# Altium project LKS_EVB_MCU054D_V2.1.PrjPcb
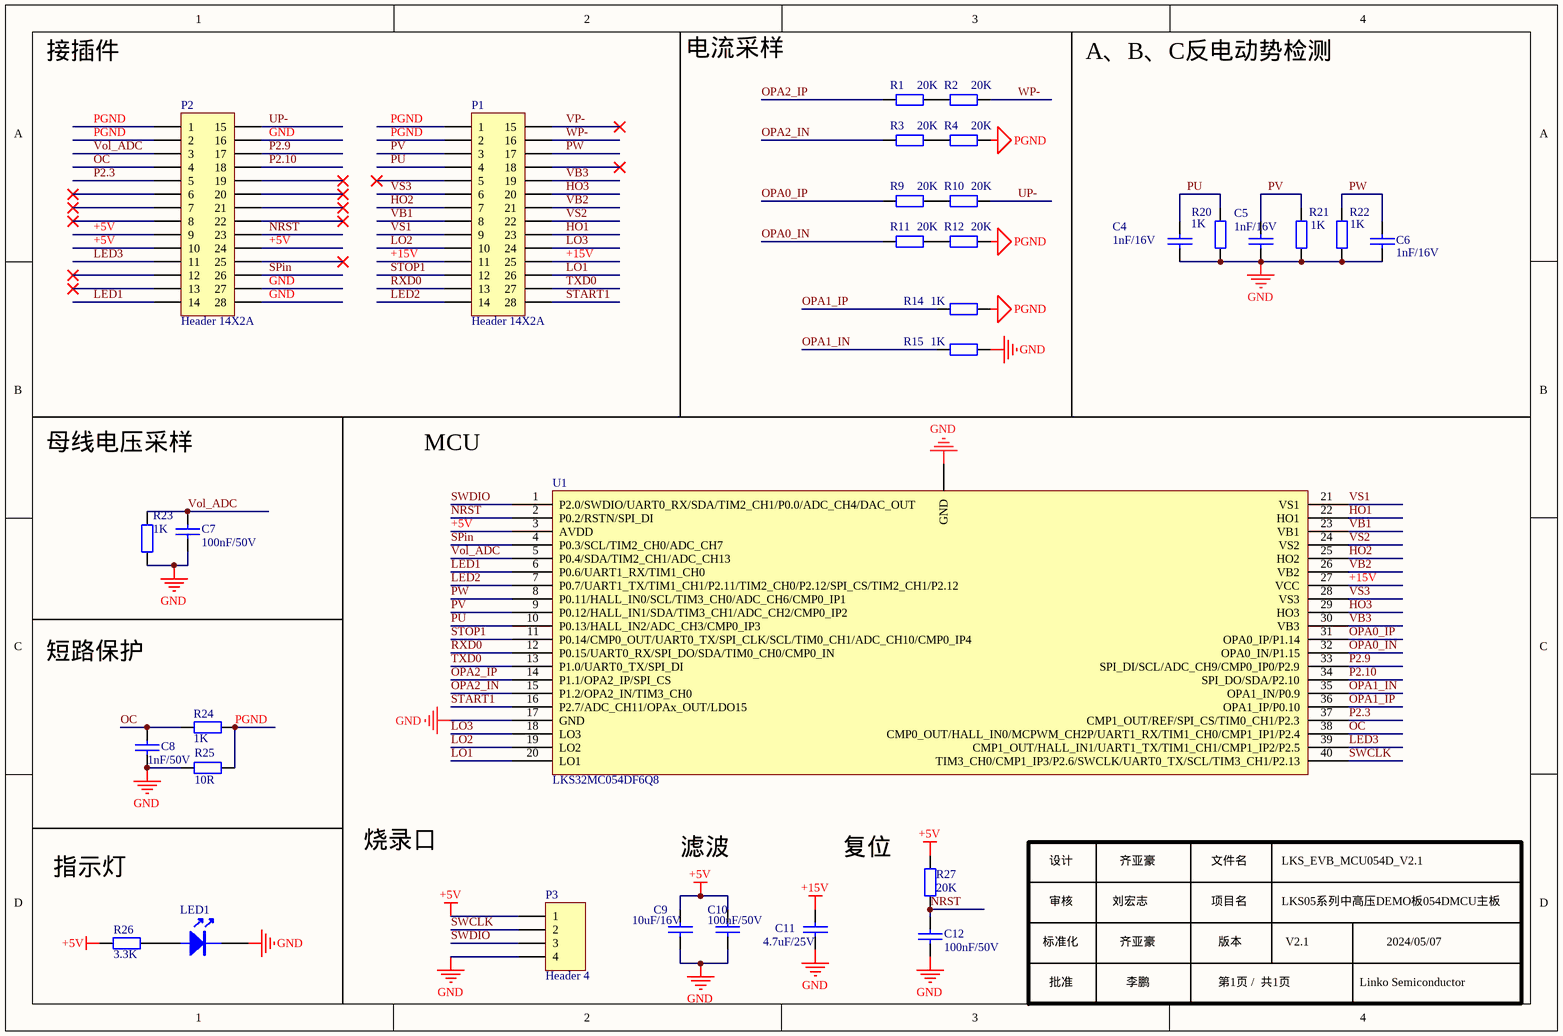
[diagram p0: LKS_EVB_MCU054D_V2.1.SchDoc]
1 sheet, 32 parts. Net scope: global (net labels, ports and power ports of the same name join across sheets).
Board file: LKS_EVB_MCU054D_V2.1.PcbDoc

## Sheet LKS_EVB_MCU054D_V2.1.SchDoc
size A4; SheetNumber: 1; SheetTotal: 1

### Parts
C4  1nF/16V  [0603C]
C5  1nF/16V  [0603C]
C6  1nF/16V  [0603C]
C7  100nF/50V  [0603C]
C8  1nF/50V  [0603C]
C9  10uF/16V  [0603C]
C10  100nF/50V  [0603C]
C11  4.7uF/25V  [0603C]
C12  100nF/50V  [0603C]
LED1  LED  [LED 0603R]  (value not drawn)
P1  Header 14X2A  [HDR 2X14 顶层]
P2  Header 14X2A  [HDR 2X14 顶层]
P3  Header 4  [HDR 1X4]
R1  20K  [0603R]
R2  20K  [0603R]
R3  20K  [0603R]
R4  20K  [0603R]
R9  20K  [0603R]
R10  20K  [0603R]
R11  20K  [0603R]
R12  20K  [0603R]
R14  1K  [0603R]
R15  1K  [0603R]
R20  1K  [0603R]
R21  1K  [0603R]
R22  1K  [0603R]
R23  1K  [0603R]
R24  1K  [0603R]
R25  10R  [0603R]
R26  3.3K  [0603R]
R27  20K  [0603R]
U1  LKS32MC054DF6Q8  [QFN40]

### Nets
+5V: C9.2 C10.2 P2.9 P2.10 P2.24 P3.1 R26.2 R27.1 U1.3(AVDD)
+15V: C11.2 P1.11 P1.25 U1.27(VCC)
GND: C4.2 C5.2 C6.2 C7.1 C8.1 C9.1 C10.1 C11.1 C12.2 LED1.2(K) P2.16 P2.27 P2.28 P3.4 R15.1 R20.2 R21.2 R22.2 R23.1 R25.2 U1.0(GND) U1.17(GND)
PGND: P1.1 P1.2 P2.1 P2.2 R4.1 R12.1 R14.1 R24.2 R25.1
HO1: P1.23 U1.22(HO1)
HO2: P1.7 U1.25(HO2)
HO3: P1.20 U1.29(HO3)
LED1: P2.14 U1.6(P0.6/UART1_RX/TIM1_CH0)
LED2: P1.14 U1.7(P0.7/UART1_TX/TIM1_CH1/P2.11/TIM2_CH0/P2.12/SPI_CS/TIM2_CH1/P2.12)
LED3: P2.11 U1.39(CMP1_OUT/HALL_IN1/UART1_TX/TIM1_CH1/CMP1_IP2/P2.5)
LO1: P1.26 U1.20(LO1)
LO2: P1.10 U1.19(LO2)
LO3: P1.24 U1.18(LO3)
NRST: C12.1 P2.23 R27.2 U1.2(P0.2/RSTN/SPI_DI)
OC: C8.2 P2.4 R24.1 U1.38(CMP0_OUT/HALL_IN0/MCPWM_CH2P/UART1_RX/TIM1_CH0/CMP1_IP1/P2.4)
OPA0_IN: R11.2 U1.32(OPA0_IN/P1.15)
OPA0_IP: R9.2 U1.31(OPA0_IP/P1.14)
OPA1_IN: R15.2 U1.35(OPA1_IN/P0.9)
OPA1_IP: R14.2 U1.36(OPA1_IP/P0.10)
OPA2_IN: R3.2 U1.15(P1.2/OPA2_IN/TIM3_CH0)
OPA2_IP: R1.2 U1.14(P1.1/OPA2_IP/SPI_CS)
P2.3: P2.5 U1.37(CMP1_OUT/REF/SPI_CS/TIM0_CH1/P2.3)
P2.9: P2.17 U1.33(SPI_DI/SCL/ADC_CH9/CMP0_IP0/P2.9)
P2.10: P2.18 U1.34(SPI_DO/SDA/P2.10)
PU: C4.1 P1.4 R20.1 U1.10(P0.13/HALL_IN2/ADC_CH3/CMP0_IP3)
PV: C5.1 P1.3 R21.1 U1.9(P0.12/HALL_IN1/SDA/TIM3_CH1/ADC_CH2/CMP0_IP2)
PW: C6.1 P1.17 R22.1 U1.8(P0.11/HALL_IN0/SCL/TIM3_CH0/ADC_CH6/CMP0_IP1)
RXD0: P1.13 U1.12(P0.15/UART0_RX/SPI_DO/SDA/TIM0_CH0/CMP0_IN)
SPin: P2.26 U1.4(P0.3/SCL/TIM2_CH0/ADC_CH7)
START1: P1.28 U1.16(P2.7/ADC_CH11/OPAx_OUT/LDO15)
STOP1: P1.12 U1.11(P0.14/CMP0_OUT/UART0_TX/SPI_CLK/SCL/TIM0_CH1/ADC_CH10/CMP0_IP4)
SWCLK: P3.2 U1.40(TIM3_CH0/CMP1_IP3/P2.6/SWCLK/UART0_TX/SCL/TIM3_CH1/P2.13)
SWDIO: P3.3 U1.1(P2.0/SWDIO/UART0_RX/SDA/TIM2_CH1/P0.0/ADC_CH4/DAC_OUT)
TXD0: P1.27 U1.13(P1.0/UART0_TX/SPI_DI)
UP-: P2.15 R10.1
VB1: P1.8 U1.23(VB1)
VB2: P1.21 U1.26(VB2)
VB3: P1.19 U1.30(VB3)
Vol_ADC: C7.2 P2.3 R23.2 U1.5(P0.4/SDA/TIM2_CH1/ADC_CH13)
VP-: P1.15
VS1: P1.9 U1.21(VS1)
VS2: P1.22 U1.24(VS2)
VS3: P1.6 U1.28(VS3)
WP-: P1.16 R2.1
NetLED1_1: LED1.1(A) R26.1
NetR1_1: R1.1 R2.2
NetR3_1: R3.1 R4.2
NetR9_1: R9.1 R10.2
NetR11_1: R11.1 R12.2

Not connected (* = marked no-connect by the designer): P1 5* 18*; P2 6* 7* 8* 12* 13* 19* 20* 21* 22* 25*

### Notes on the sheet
- 接插件
- 母线电压采样
- 短路保护
- 烧录口
- 指示灯
- 滤波
- 复位
- 设计
- 审核
- 刘宏志
- 齐亚豪
- 文件名
- 项目名
- LKS_EVB_MCU054D_V2.1
- LKS05系列中高压DEMO板054DMCU主板
- 标准化
- 批准
- 李鹏
- 版本
- 第1页 /  共1页
- V2.1
- Linko Semiconductor
- 2024/05/07
- Labels drawn without touching a wire or pin: A、B、C反电动势检测, MCU, 电流采样

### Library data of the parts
C4-C6 = CAP: Capacitor
C7-C12 = C: Capacitor
LED1 = LED: LED_Light
P1 P2 = Header 14X2A: Header, 14-Pin, Dual row
P3 = Header 4: Header, 4-Pin
R1-R4 R9-R12 R14 R15 R20-R25 = Res: Resistor; Value: K
R26 R27 = Res: Resistor; Value: 330
U1 = LKS32MC054DF6Q8: 芯片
